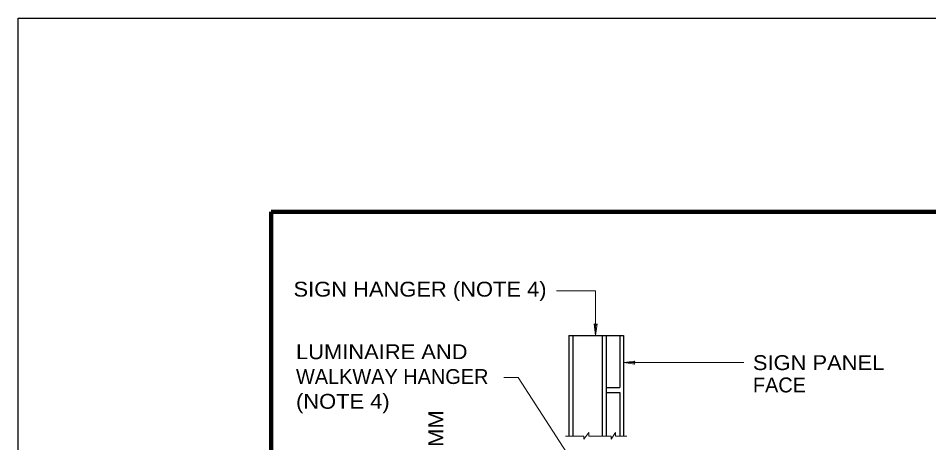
# Model space of a CAD drawing. Extents: x 312601.858 to 312602.699, y 144420.109 to 144420.704.
# Drawn here: x 312601.8578 to 312602.0414, y 144420.6179 to 144420.7035 of the extents above; entities that cross this region are included whole.
import ezdxf
from ezdxf.enums import TextEntityAlignment as Align

# ---------------------------------------------------------------- set-up
doc = ezdxf.new("R2010")
doc.units = 0
doc.header["$LTSCALE"] = 0.0012
for name, color, linetype, lineweight in [('1', 7, 'Continuous', 13), ('2', 7, 'Continuous', 13), ('39', 7, 'Continuous', 13)]:
    doc.layers.add(name, color=color, linetype=linetype, lineweight=lineweight)

msp = doc.modelspace()

# ---------------------------------------------------------------- linework, layer by layer
at = {"layer": '1'}
for p, q in [((312601.9742, 144420.6486), (312601.9663, 144420.6486)), ((312601.9742, 144420.6486), (312601.9742, 144420.6396)), ((312601.9798, 144420.6341), (312602.0041, 144420.6341)), ((312601.9586, 144420.6311), (312601.9557, 144420.6311)), ((312601.9586, 144420.6311), (312601.9724, 144420.6098)), ((312601.9681, 144420.6193), (312601.9718, 144420.6193)), ((312601.9718, 144420.6187), (312601.9728, 144420.62)), ((312601.9718, 144420.6187), (312601.9718, 144420.6193)), ((312601.9728, 144420.6193), (312601.9728, 144420.62)), ((312601.9728, 144420.6193), (312601.9773, 144420.6193)), ((312601.9773, 144420.6187), (312601.9782, 144420.62)), ((312601.9773, 144420.6187), (312601.9773, 144420.6193)), ((312601.9782, 144420.6193), (312601.9782, 144420.62)), ((312601.9782, 144420.6193), (312601.9805, 144420.6193))]:
    msp.add_line(p, q, dxfattribs=at)
at = {"layer": '1', "lineweight": 25}
for p, q in [((312601.9688, 144420.6396), (312601.9798, 144420.6396)), ((312601.9688, 144420.6396), (312601.9688, 144420.6193)), ((312601.9696, 144420.6396), (312601.9696, 144420.6193)), ((312601.9755, 144420.6396), (312601.9755, 144420.6193)), ((312601.9763, 144420.6396), (312601.9763, 144420.6193)), ((312601.9791, 144420.6396), (312601.9791, 144420.6291)), ((312601.9798, 144420.6396), (312601.9798, 144420.6193)), ((312601.9763, 144420.6291), (312601.9791, 144420.6291)), ((312601.9763, 144420.6281), (312601.9791, 144420.6281)), ((312601.9791, 144420.6281), (312601.9791, 144420.6193))]:
    msp.add_line(p, q, dxfattribs=at)
at = {"layer": '1'}
for points in [[(312601.9745, 144420.6419), (312601.9742, 144420.6396), (312601.9739, 144420.6419), (312601.9742, 144420.6416)], [(312601.9821, 144420.6338), (312601.9798, 144420.6341), (312601.9821, 144420.6344), (312601.9818, 144420.6341)]]:
    msp.add_lwpolyline(points, close=True, dxfattribs=at)
at = {"layer": '39', "lineweight": 25}
for p, q in [((312601.8578, 144420.1095), (312601.8578, 144420.7035)), ((312601.8578, 144420.7035), (312602.6988, 144420.7035))]:
    msp.add_line(p, q, dxfattribs=at)
at = {"layer": '39', "lineweight": 158}
for p, q in [((312601.9088, 144420.1247), (312601.9088, 144420.6645)), ((312601.9088, 144420.6645), (312602.6838, 144420.6645))]:
    msp.add_line(p, q, dxfattribs=at)

# ---------------------------------------------------------------- texts
at = {"layer": '2', "width": 1.1}
msp.add_text('SIGN HANGER (NOTE 4)', height=0.003, dxfattribs=at).set_placement((312601.9388, 144420.6474), align=Align.CENTER)
for s, p in [('LUMINAIRE AND', (312601.9138, 144420.6348)), ('SIGN PANEL', (312602.0059, 144420.6326)), ('(NOTE 4)', (312601.9138, 144420.6248))]:
    msp.add_text(s, height=0.003, dxfattribs=at).set_placement(p)
at = {"layer": '2'}
for s, p in [('WALKWAY HANGER', (312601.9138, 144420.6298)), ('FACE', (312602.0059, 144420.6281))]:
    msp.add_text(s, height=0.003, dxfattribs=at).set_placement(p)
at = {"layer": '2', "width": 1.1}
msp.add_text('75 MM', height=0.003, rotation=90, dxfattribs=at).set_placement((312601.9435, 144420.61775), align=Align.CENTER)

doc.saveas('drawing.dxf')
